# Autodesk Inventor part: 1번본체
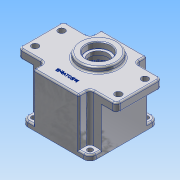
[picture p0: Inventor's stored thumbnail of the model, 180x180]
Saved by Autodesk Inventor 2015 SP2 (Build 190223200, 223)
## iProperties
Created: 2015-06
Part Number: 1번본체
Material: 알루미늄 6061
Document SubType Name: Modeling
Designer: AMC
Density: 2.7 g/cm^3
Appearance: 알루미늄 - 평지
Mass: 704.51 g
Surface Area: 673.549 cm^2
Volume: 260.93 cm^3
Author: AMC
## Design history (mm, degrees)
sketch "스케치5"
  geometry: L1 (0, 0)-(90, 0); L2 (90, 0)-(90, 90); L3 (90, 90)-(0, 90); L4 (0, 90)-(0, 0)
  constraints: 8 end point, 2 parallel, 1 horizontal, 1 perpendicular
  dimensions: "d29" = 90 distance of L2.end L3.end; "d30" = 90 distance of L3.end L1.start
extrude "돌출5" new body sketch "스케치5" distance "d31" = 70; taper "d32" = 0 deg
sketch "스케치6"
  geometry: L1 (0, 90)-(15, 90); L2 (15, 90)-(15, 75); L3 (15, 75)-(0, 75); L4 (0, 75)-(0, 90); L5 (90, 90)-(75, 90); L6 (75, 90)-(75, 75); L7 (75, 75)-(90, 75); L8 (90, 75)-(90, 90); L9 (0, 90)-(0, 0) reference; L10 (0, 45)-(20.47, 45); L11 (15, 0)-(15, 15); L12 (15, 15)-(0, 15); L13 (0, 0)-(15, 0); L14 (0, 15)-(0, 0); L15 (75, 0)-(75, 15); L16 (75, 15)-(90, 15); L17 (90, 15)-(90, 0); L18 (90, 0)-(75, 0)
  constraints: 34 end point, 7 symmetric about line, 4 parallel, 3 horizontal, 2 perpendicular, 2 point on line, 1 midpoint
  dimensions: "d40" = 15 distance of L2.end L3.end; "d41" = 15 distance of L1.end L2.end; "d42" = 15 distance of L5.start L5.end
extrude "돌출6" cut sketch "스케치6" distance "d43" = 63; taper "d44" = 0 deg
sketch "스케치7"
  geometry: L1 (-20, 75)-(110, 75); L2 (110, 75)-(110, 15); L3 (110, 15)-(-20, 15); L4 (-20, 15)-(-20, 75); L5 (15, 75)-(0, 75) reference; L6 (75, 15)-(90, 15) reference; L7 (90, 15)-(75, 15) reference; L8 (75, 15)-(75, 0) reference; L9 (75, 0)-(15, 0) reference; L10 (15, 0)-(15, 15) reference; L11 (15, 15)-(0, 15) reference; L12 (0, 15)-(0, 75) reference; L13 (0, 75)-(15, 75) reference; L14 (15, 75)-(15, 90) reference; L15 (15, 90)-(75, 90) reference; L16 (75, 90)-(75, 75) reference; L17 (75, 75)-(90, 75) reference; L18 (90, 75)-(90, 15) reference; 5 further points
  constraints: 8 end point, 4 midpoint, 2 collinear, 2 parallel, 2 vertical alignment, 1 horizontal, 1 perpendicular
  dimensions: "d45" = 130 distance of L1.start L1.end
extrude "돌출7" join sketch "스케치7" distance "d46" = 12; taper "d47" = 0 deg
sketch "스케치8"
  geometry: L1 (75, 90)-(75, 75) reference; L2 (75, 75)-(110, 75) reference; L3 (110, 75)-(110, 15) reference; L4 (110, 15)-(75, 15) reference; L5 (75, 15)-(75, 0) reference; L6 (75, 0)-(15, 0) reference; L7 (15, 0)-(15, 15) reference; L8 (15, 15)-(-20, 15) reference; L9 (-20, 15)-(-20, 75) reference; L10 (-20, 75)-(15, 75) reference; L11 (15, 75)-(15, 90) reference; L12 (15, 90)-(75, 90) reference; L13 (110, 75)-(110, 15) reference; C1 r 25 at (45, 56); 3 further points
  constraints: 2 midpoint, 1 centre point, 1 vertical alignment
  dimensions: "d48" = 50 diameter of C1; "d62" = 11 vertical distance of point (110, 45) C1.centre
extrude "돌출8" join sketch "스케치8" distance "d49" = 7; taper "d50" = 0 deg
fillet "모깎기3" dims "d51" = 5
fillet "모깎기4" dims "d52" = 2
node "작업 평면1"
fillet "모깎기5" dims "d76" = 8
fillet "모깎기6" dims "d102" = 2
fillet "모깎기7" dims "d103" = 2
sketch "스케치17"
  geometry: L1 (90, 82)-(90, 75) reference; L2 (90, 75)-(90, 15) reference; L3 (90, 15)-(90, 8) reference; L4 (82, 0)-(73, 0) reference; L5 (73, 0)-(17, 0) reference; L6 (17, 0)-(8, 0) reference; L7 (0, 8)-(0, 15) reference; L8 (0, 15)-(0, 75) reference; L9 (0, 75)-(10, 75) reference; L10 (15, 80)-(15, 88) reference; L11 (8, 90)-(17, 90) reference; L12 (0, 75)-(0, 82) reference; L13 (73, 90)-(82, 90) reference; L14 (75, 88)-(75, 80) reference; L15 (80, 75)-(90, 75) reference; L16 (90, 15)-(80, 15) reference; L17 (75, 10)-(75, 2) reference; L18 (15, 2)-(15, 10) reference; L19 (10, 15)-(0, 15) reference; L20 (17, 90)-(73, 90) reference; A1 r 8 centre (82, 8) between (82, 0) and (90, 8) reference; A2 r 8 centre (8, 8) between (0, 8) and (8, 0) reference; A3 r 5 centre (10, 80) between (10, 75) and (15, 80) reference; A4 r 2 centre (17, 88) between (17, 90) and (15, 88) reference; A5 r 8 centre (8, 82) between (8, 90) and (0, 82) reference; A6 r 8 centre (82, 82) between (90, 82) and (82, 90) reference; A7 r 2 centre (73, 88) between (75, 88) and (73, 90) reference; A8 r 5 centre (80, 80) between (75, 80) and (80, 75) reference; A9 r 5 centre (80, 10) between (80, 15) and (75, 10) reference; A10 r 2 centre (73, 2) between (73, 0) and (75, 2) reference; A11 r 2 centre (17, 2) between (15, 2) and (17, 0) reference; A12 r 5 centre (10, 10) between (15, 10) and (10, 15) reference; 5 further points
  constraints: 4 coincident
hole "구멍2" sketch "스케치17" at (8, 82), (8, 8), (82, 82), (82, 8) diameter "d104" = 7; stored, may be unused: countersink angle "d108" = 90 deg, drill point angle "d110" = 118 deg; dims "d105" = 12, "d106" = 4, "d107" = 2, "d109" = 15
sketch "스케치18"
  geometry: L1 (73, 80)-(73, 88) reference; L2 (17, 88)-(17, 80) reference; L3 (-15, 73)-(10, 73) reference; L4 (-18, 20)-(-18, 70) reference; L5 (-15, 17)-(10, 17) reference; L6 (17, 10)-(17, 2) reference; L7 (73, 2)-(73, 10) reference; L8 (105, 17)-(80, 17) reference; L9 (108, 70)-(108, 20) reference; L10 (105, 73)-(80, 73) reference; L11 (-30.692, 45)-(122.737, 45); L12 (17, 2)-(73, 2) reference; L13 (73, 88)-(17, 88) reference; C1 r 27 at (45, 56) reference; C2 r 4.5 at (-10, 62.5); C3 r 4.5 at (-10, 27.5); C4 r 4.5 at (100, 62.5); C5 r 4.5 at (100, 27.5); A1 r 7 centre (10, 80) between (10, 73) and (17, 80) reference; A2 r 3 centre (-15, 70) between (-15, 73) and (-18, 70) reference; A3 r 3 centre (-15, 20) between (-18, 20) and (-15, 17) reference; A4 r 7 centre (10, 10) between (17, 10) and (10, 17) reference; A5 r 7 centre (80, 10) between (80, 17) and (73, 10) reference; A6 r 3 centre (105, 20) between (105, 17) and (108, 20) reference; A7 r 3 centre (105, 70) between (108, 70) and (105, 73) reference; A8 r 7 centre (80, 80) between (73, 80) and (80, 73) reference; 2 further points
  constraints: 4 centre point, 2 end point, 2 equal radius, 2 horizontal alignment, 2 vertical alignment, 1 midpoint, 1 perpendicular, 1 point on line
  dimensions: "d116" = 110 distance of C2.centre C4.centre; "d117" = 35 distance of C5.centre C4.centre; "d118" = 55 horizontal distance of C1.centre C4.centre; "d119" = 17.5 distance from line of L11 C2.centre; "d120" = 9 diameter of C2; "d121" = 9 diameter of C4
extrude "돌출14" cut sketch "스케치18" stored distance "d122" = 45; taper "d123" = 0 deg
sketch "스케치19"
  geometry: L1 (-8, 0)-(-82, 0) reference; L2 (-90, 8)-(-90, 82) reference; L3 (-82, 90)-(-8, 90) reference; L4 (0, 82)-(0, 8) reference; C1 r 3.5 at (-82, 82) reference; C2 r 3.5 at (-8, 82) reference; C3 r 3.5 at (-8, 8) reference; C4 r 3.5 at (-82, 8) reference; C5 r 40 at (-45, 45); A1 r 8 centre (-82, 8) between (-90, 8) and (-82, 0) reference; A2 r 8 centre (-82, 82) between (-82, 90) and (-90, 82) reference; A3 r 8 centre (-8, 82) between (0, 82) and (-8, 90) reference; A4 r 8 centre (-8, 8) between (-8, 0) and (0, 8) reference; 3 further points
  constraints: 2 midpoint, 1 centre point, 1 horizontal alignment, 1 vertical alignment
  dimensions: "d124" = 80 diameter of C5
extrude "돌출15" cut sketch "스케치19" distance "d125" = 9; taper "d126" = 0 deg
sketch "스케치20"
  geometry: L1 (-45, -30)-(-45, 30) reference; L2 (-30, 35)-(-30, 43) reference; L3 (-28, 45)-(28, 45) reference; L4 (30, 43)-(30, 35) reference; L5 (35, 30)-(45, 30) reference; L6 (45, 30)-(45, -30) reference; L7 (45, -30)-(35, -30) reference; L8 (30, -35)-(30, -43) reference; L9 (28, -45)-(-28, -45) reference; L10 (-30, -43)-(-30, -35) reference; L11 (-35, -30)-(-45, -30) reference; L12 (-45, 30)-(-35, 30) reference; C1 r 39 at (0, 0); C2 r 40 at (0, 0) reference; A1 r 5 centre (-35, -35) between (-30, -35) and (-35, -30) reference; A2 r 5 centre (-35, 35) between (-35, 30) and (-30, 35) reference; A3 r 2 centre (-28, 43) between (-28, 45) and (-30, 43) reference; A4 r 2 centre (28, 43) between (30, 43) and (28, 45) reference; A5 r 5 centre (35, 35) between (30, 35) and (35, 30) reference; A6 r 5 centre (35, -35) between (35, -30) and (30, -35) reference; A7 r 2 centre (28, -43) between (28, -45) and (30, -43) reference; A8 r 2 centre (-28, -43) between (-30, -43) and (-28, -45) reference; 1 further point
  constraints: 1 centre point, 1 coincident
  dimensions: "d127" = 78 diameter of C1
extrude "돌출16" cut sketch "스케치20" distance "d128" = 52; taper "d129" = 0 deg
sketch "스케치21"
  geometry: L1 (-65, -25)-(-65, 25) reference; L2 (-30, 35)-(-30, 43) reference; L3 (-28, 45)-(28, 45) reference; L4 (30, 43)-(30, 35) reference; L5 (35, 30)-(60, 30) reference; L6 (65, 25)-(65, -25) reference; L7 (60, -30)-(35, -30) reference; L8 (30, -35)-(30, -43) reference; L9 (28, -45)-(-28, -45) reference; L10 (-30, -43)-(-30, -35) reference; L11 (-35, -30)-(-60, -30) reference; L12 (-60, 30)-(-35, 30) reference; C1 r 39 at (0, 0) reference; C2 r 4.5 at (-55, 17.5) reference; C3 r 4.5 at (-55, -17.5) reference; C4 r 4.5 at (55, -17.5) reference; C5 r 4.5 at (55, 17.5) reference; A1 r 5 centre (-35, -35) between (-30, -35) and (-35, -30) reference; A2 r 5 centre (-60, -25) between (-65, -25) and (-60, -30) reference; A3 r 5 centre (-60, 25) between (-60, 30) and (-65, 25) reference; A4 r 5 centre (-35, 35) between (-35, 30) and (-30, 35) reference; A5 r 2 centre (-28, 43) between (-28, 45) and (-30, 43) reference; A6 r 2 centre (28, 43) between (30, 43) and (28, 45) reference; A7 r 5 centre (35, 35) between (30, 35) and (35, 30) reference; A8 r 5 centre (60, 25) between (65, 25) and (60, 30) reference; A9 r 5 centre (60, -25) between (60, -30) and (65, -25) reference; A10 r 5 centre (35, -35) between (35, -30) and (30, -35) reference; A11 r 2 centre (28, -43) between (28, -45) and (30, -43) reference; A12 r 2 centre (-28, -43) between (-30, -43) and (-28, -45) reference; A13 r 20.5 centre (0, 11) between (7.402, -8.117) and (-7.402, -8.117); A14 r 14 centre (0, -20) between (-7.402, -8.117) and (7.402, -8.117); 1 further point
  constraints: 4 point on circle, 2 centre point, 2 vertical alignment
  dimensions: "d130" = 41 diameter of A13; "d131" = 28 diameter of A14; "d132" = 20 distance of A14.centre C1.centre; "d133" = 11 distance of C1.centre A13.centre
extrude "돌출17" join sketch "스케치21" distance "d134" = 7; taper "d135" = 0 deg
node "작업 평면2"
sketch "스케치22"
  geometry: L1 (-12, -13)-(-12, 14) reference; L2 (-14, 16)-(-19, 16) reference; L3 (-19, 16)-(-19, 66) reference; L4 (-19, 66)-(-14, 66) reference; L5 (-12, 68)-(-12, 73) reference; L6 (-10, 75)-(58, 75) reference; L7 (58, 75)-(58, 70) reference; L8 (58, 70)-(49, 70) reference; L9 (49, 70)-(49, 69) reference; L10 (49, 69)-(-3, 69) reference; L11 (-3, 69)-(-3, 61.5) reference; L12 (-3, 61.5)-(4, 61.5) reference; L13 (4, 61.5)-(4, -4) reference; L14 (4, -4)-(-3, -4) reference; L15 (-3, -4)-(-3, -9) reference; L16 (-3, -9)-(49, -9) reference; L17 (49, -9)-(49, -10) reference; L18 (49, -10)-(58, -10) reference; L19 (58, -10)-(58, -15) reference; L20 (58, -15)-(-10, -15) reference; L21 (-19, 41)-(18.673, 41); L22 (-19, 66)-(-19, 16) reference; L23 (-19, 57)-(-11, 57); L24 (-12, 68)-(-12, 14) reference; L25 (-11, 53.5)-(-6, 53.5); L26 (-6, 53.5)-(-6, 58.5); L27 (-6, 58.5)-(4, 58.5); L28 (-11, 57)-(-11, 53.5); L29 (4, -4)-(4, 21.883) reference; L30 (58, 67)-(58, -7) reference; L31 (-12, 10)-(62.879, 10); L32 (4, 21)-(-3, 21); L33 (-3, 21)-(-3, 19.5); L34 (-3, 19.5)-(-4, 19.5); L35 (-4, 19.5)-(-4, 10); L36 (-19, 57)-(-19, 41); L37 (4, 21)-(4, 10); L38 (4, 58.5)-(4, 41); A1 r 2 centre (-10, -13) between (-12, -13) and (-10, -15) reference; A2 r 2 centre (-14, 14) between (-12, 14) and (-14, 16) reference; A3 r 2 centre (-14, 68) between (-14, 66) and (-12, 68) reference; A4 r 2 centre (-10, 73) between (-10, 75) and (-12, 73) reference; 1 further point
  constraints: 28 end point, 9 point on line, 8 perpendicular, 3 horizontal, 2 midpoint, 1 collinear
  dimensions: "d136" = 10 distance of L26.end L27.end; "d137" = 8 distance of L23.start L23.end; "d138" = 32 diameter of L23 L21; "d139" = 35 diameter of L27 L21; "d140" = 25 diameter of L25 L21; "d141" = 40 diameter of point (58, 30) L31; "d142" = 19 diameter of L34 L31; "d143" = 22 diameter of L32 L31; "d144" = 7 distance of L32.start L32.end; "d145" = 1 distance of L33.end L34.end
  node "절단 모서리 투영21"
revolve "회전3" stored, may be unused: angle "d146" = 90 deg
revolve "회전4" stored, may be unused: angle "d147" = 90 deg
chamfer "모따기1" distance "d148" = 1; stored, may be unused: second distance "d149" = 2, angle "d150" = 45 deg
fillet "모깎기8" dims "d151" = 3
fillet "모깎기9" dims "d152" = 2
sketch "스케치23" dims "d153" = 70
  geometry: L1 (-45, -30)-(-45, 30) reference; L2 (-30, 35)-(-30, 43) reference; L3 (-28, 45)-(28, 45) reference; L4 (30, 43)-(30, 35) reference; L5 (35, 30)-(45, 30) reference; L6 (45, 30)-(45, -30) reference; L7 (45, -30)-(35, -30) reference; L8 (30, -35)-(30, -43) reference; L9 (28, -45)-(-28, -45) reference; L10 (-30, -43)-(-30, -35) reference; L11 (0, 0)-(0, 55.728); L12 (0, 0)-(58.143, 58.143); L13 (-35, -30)-(-45, -30) reference; L14 (-45, 30)-(-35, 30) reference; C1 r 40 at (0, 0) reference; A1 r 39 centre (0, 0) between (32.777, 21.134) and (21.134, 32.777) reference; A2 r 5 centre (-35, -35) between (-30, -35) and (-35, -30) reference; A3 r 5 centre (-35, 35) between (-35, 30) and (-30, 35) reference; A4 r 2 centre (-28, 43) between (-28, 45) and (-30, 43) reference; A5 r 2 centre (28, 43) between (30, 43) and (28, 45) reference; A6 r 5 centre (35, 35) between (30, 35) and (35, 30) reference; A7 r 5 centre (35, -35) between (35, -30) and (30, -35) reference; A8 r 2 centre (28, -43) between (28, -45) and (30, -43) reference; A9 r 2 centre (-28, -43) between (-30, -43) and (-28, -45) reference; A10 r 4 centre (24.749, 24.749) between (21.809, 27.462) and (27.462, 21.809); A11 r 3.5 centre (29.836, 19.238) between (32.777, 21.134) and (27.462, 21.809); A12 r 3.5 centre (19.238, 29.836) between (21.809, 27.462) and (21.134, 32.777); 1 further point
  constraints: 8 point on circle, 4 end point, 4 tangent, 3 centre point, 1 coincident, 1 point on line, 1 vertical, 3 other
  dimensions: "d154" = 45 deg angle of L11 L12; "d155" = 8 diameter of A10; "d156" = 7 diameter of A11; "d157" = 7 diameter of A12
extrude "돌출18" join sketch "스케치23" stored distance "d158" = 7; taper "d159" = 0 deg
sketch "스케치24"
  geometry: L1 (-45, -30)-(-45, 30) reference; L2 (-30, 35)-(-30, 43) reference; L3 (-28, 45)-(28, 45) reference; L4 (30, 43)-(30, 35) reference; L5 (35, 30)-(45, 30) reference; L6 (45, 30)-(45, -30) reference; L7 (45, -30)-(35, -30) reference; L8 (30, -35)-(30, -43) reference; L9 (28, -45)-(-28, -45) reference; L10 (-30, -43)-(-30, -35) reference; L11 (-35, -30)-(-45, -30) reference; L12 (-45, 30)-(-35, 30) reference; C1 r 40 at (0, 0) reference; A1 r 4 centre (24.749, 24.749) between (21.809, 27.462) and (27.462, 21.809) reference; A2 r 3.5 centre (19.238, 29.836) between (21.809, 27.462) and (21.134, 32.777) reference; A3 r 39 centre (0, 0) between (21.134, 32.777) and (-21.134, 32.777) reference; A4 r 3.5 centre (-19.238, 29.836) between (-21.134, 32.777) and (-21.809, 27.462) reference; A5 r 4 centre (-24.749, 24.749) between (-27.462, 21.809) and (-21.809, 27.462) reference; A6 r 3.5 centre (-29.836, 19.238) between (-27.462, 21.809) and (-32.777, 21.134) reference; A7 r 39 centre (0, 0) between (-32.777, 21.134) and (-32.777, -21.134) reference; A8 r 3.5 centre (-29.836, -19.238) between (-32.777, -21.134) and (-27.462, -21.809) reference; A9 r 4 centre (-24.749, -24.749) between (-21.809, -27.462) and (-27.462, -21.809) reference; A10 r 3.5 centre (-19.238, -29.836) between (-21.809, -27.462) and (-21.134, -32.777) reference; A11 r 39 centre (0, 0) between (-21.134, -32.777) and (21.134, -32.777) reference; A12 r 3.5 centre (19.238, -29.836) between (21.134, -32.777) and (21.809, -27.462) reference; A13 r 4 centre (24.749, -24.749) between (27.462, -21.809) and (21.809, -27.462) reference; A14 r 3.5 centre (29.836, -19.238) between (27.462, -21.809) and (32.777, -21.134) reference; A15 r 39 centre (0, 0) between (32.777, -21.134) and (32.777, 21.134) reference; A16 r 3.5 centre (29.836, 19.238) between (32.777, 21.134) and (27.462, 21.809) reference; A17 r 5 centre (-35, -35) between (-30, -35) and (-35, -30) reference; A18 r 5 centre (-35, 35) between (-35, 30) and (-30, 35) reference; A19 r 2 centre (-28, 43) between (-28, 45) and (-30, 43) reference; A20 r 2 centre (28, 43) between (30, 43) and (28, 45) reference; A21 r 5 centre (35, 35) between (30, 35) and (35, 30) reference; A22 r 5 centre (35, -35) between (35, -30) and (30, -35) reference; A23 r 2 centre (28, -43) between (28, -45) and (30, -43) reference; A24 r 2 centre (-28, -43) between (-30, -43) and (-28, -45) reference; 5 further points
  constraints: 4 coincident
hole "구멍3" sketch "스케치24" at (-24.749, 24.749), (24.749, 24.749), (24.749, -24.749), (-24.749, -24.749) diameter "d163" = 3.242; stored, may be unused: countersink angle "d167" = 90 deg, drill point angle "d169" = 118 deg; dims "d164" = 12, "d165" = 4, "d166" = 2, "d168" = 15
fillet "모깎기10" dims "d170" = 4
fillet "모깎기11" dims "d171" = 0.3
fillet "모깎기12" dims "d172" = 0.3
sketch "스케치26"
  geometry: L1 (17, 88)-(17, 80) reference; L2 (-15, 73)-(10, 73) reference; L3 (-18, 20)-(-18, 70) reference; L4 (-15, 17)-(10, 17) reference; L5 (17, 10)-(17, 2) reference; L6 (17, 2)-(73, 2) reference; L7 (73, 2)-(73, 10) reference; L8 (105, 17)-(80, 17) reference; L9 (108, 70)-(108, 20) reference; L10 (105, 73)-(80, 73) reference; L11 (73, 80)-(73, 88) reference; L12 (73, 88)-(17, 88) reference; L13 (17, 0)-(73, 0) reference; C1 r 16 at (45, 56) reference; C2 r 4.5 at (100, 62.5) reference; C3 r 4.5 at (100, 27.5) reference; C4 r 4.5 at (-10, 27.5) reference; C5 r 4.5 at (-10, 62.5) reference; C6 r 27 at (45, 56) reference; A1 r 7 centre (10, 80) between (10, 73) and (17, 80) reference; A2 r 3 centre (-15, 70) between (-15, 73) and (-18, 70) reference; A3 r 3 centre (-15, 20) between (-18, 20) and (-15, 17) reference; A4 r 7 centre (10, 10) between (17, 10) and (10, 17) reference; A5 r 7 centre (80, 10) between (80, 17) and (73, 10) reference; A6 r 3 centre (105, 20) between (105, 17) and (108, 20) reference; A7 r 3 centre (105, 70) between (108, 70) and (105, 73) reference; A8 r 7 centre (80, 80) between (73, 80) and (80, 73) reference; 2 further points
  constraints: 1 vertical alignment, 1 other
  dimensions: "d176" = 15 distance from line of L13 point (45, 15)
feature "엠보싱2" sketch "스케치26" dims "d40" = 15, "d41" = 15, "d42" = 15, "d177" = 0.5, "d178" = 0
fillet "모깎기13" dims "d179" = 2
fillet "모깎기14" dims "d180" = 2
fillet "모깎기15" dims "d181" = 2
fillet "모깎기16" dims "d182" = 2
fillet "모깎기17" dims "d183" = 2
node "솔리드2"
pattern_circular "원형 패턴3" dims angle "d161" = 360 deg
node "절단 모서리 투영3"
node "절단 모서리 투영4"
node "절단 모서리 투영16"
node "절단 모서리 투영17"
node "절단 모서리 투영18"
node "절단 모서리 투영19"
node "절단 모서리 투영20"
node "절단 모서리 투영22"
node "절단 모서리 투영23"
node "절단 모서리 투영25"
